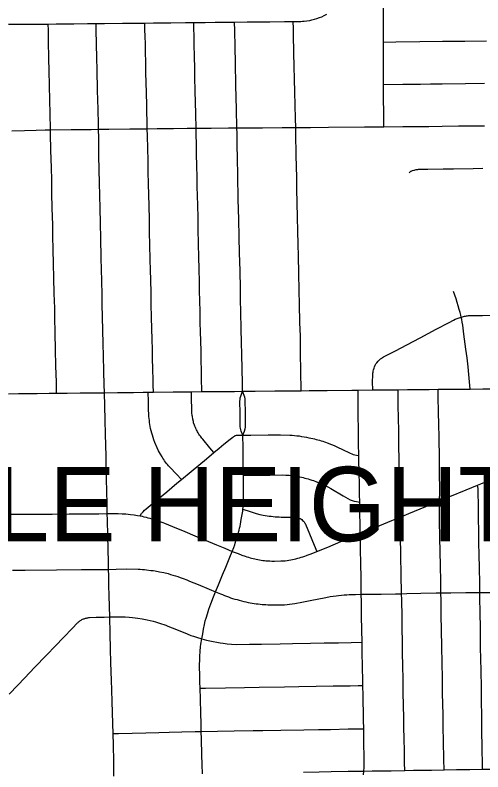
# Model space of a CAD drawing. Extents: x 0 to 34, y 0 to 22.
# Drawn here: x 2.953 to 3.548, y 19.442 to 20.406 of the extents above; entities that cross this region are included whole.
import ezdxf

# ---------------------------------------------------------------- set-up
doc = ezdxf.new("R2010")
doc.units = 0
for name, color, linetype in [('GM_X_City_Street', 7, 'Continuous'), ('GM_X_Corporation_Text', 7, 'Continuous'), ('GM_X_State_Route', 7, 'Continuous')]:
    doc.layers.add(name, color=color, linetype=linetype)

msp = doc.modelspace()

# ---------------------------------------------------------------- linework, layer by layer
at = {"layer": 'GM_X_City_Street'}
for p, q in [((3.17725, 19.92651), (3.19038, 19.9266)), ((3.12227, 19.92591), (3.12865, 19.92602))]:
    msp.add_line(p, q, dxfattribs=at)
for points in [[(3.42223, 20.26388), (3.42199, 20.31784), (3.42193, 20.33158), (3.42179, 20.36208), (3.42175, 20.3717), (3.42163, 20.41614), (3.42168, 20.43603)], [(2.94423, 20.39438), (2.96155, 20.39449), (2.97782, 20.39459), (2.99479, 20.3947), (3.00499, 20.3948), (3.02745, 20.395), (3.04483, 20.39525), (3.05581, 20.39539), (3.06637, 20.39548), (3.08928, 20.39564), (3.10812, 20.39578), (3.11781, 20.39591), (3.12868, 20.39604), (3.15111, 20.39628), (3.16957, 20.39649), (3.18009, 20.3966), (3.19451, 20.39676), (3.2073, 20.3969), (3.22292, 20.39707), (3.23217, 20.39717), (3.24828, 20.39733), (3.27721, 20.39763), (3.29566, 20.39782), (3.30678, 20.39793), (3.31425, 20.39804), (3.31638, 20.39812), (3.3188, 20.39828), (3.32089, 20.39846), (3.32426, 20.39884), (3.32787, 20.3994), (3.33053, 20.39992), (3.33381, 20.40081), (3.33703, 20.40181), (3.34025, 20.4029), (3.34319, 20.40409), (3.34604, 20.40542), (3.34957, 20.40723)], [(3.0054, 19.92458), (3.0051, 19.93869), (3.00464, 19.9597), (3.0042, 19.97977), (3.00363, 20.00142), (3.00323, 20.02112), (3.00299, 20.03301), (3.0025, 20.05176), (3.002, 20.07139), (3.00162, 20.08944), (3.00125, 20.10782), (3.00083, 20.12461), (3.00047, 20.13909), (2.99998, 20.16036), (2.99955, 20.17923), (2.99918, 20.19603), (2.99883, 20.21195), (2.99827, 20.23373), (2.99777, 20.25531), (2.99766, 20.25996), (2.9972, 20.28124), (2.99685, 20.29727), (2.9964, 20.31703), (2.99593, 20.33466), (2.99561, 20.35122), (2.99517, 20.37255), (2.99493, 20.38678), (2.99479, 20.3947)], [(3.07841, 19.43691), (3.0782, 19.45599), (3.07782, 19.47641), (3.07754, 19.49136), (3.07718, 19.50384), (3.07666, 19.51847), (3.07618, 19.53146), (3.07561, 19.54714), (3.07519, 19.55865), (3.07467, 19.58195), (3.07429, 19.59862), (3.07379, 19.61874), (3.07332, 19.63968), (3.07292, 19.65289), (3.0725, 19.66685), (3.07211, 19.67996), (3.07183, 19.69189), (3.07164, 19.70035), (3.07143, 19.70939), (3.07104, 19.72586), (3.07065, 19.74325), (3.07021, 19.76311), (3.07003, 19.77135), (3.06978, 19.78346), (3.06942, 19.80013), (3.06911, 19.8149), (3.06871, 19.83074), (3.06837, 19.84445), (3.06804, 19.85847), (3.06771, 19.87249), (3.06727, 19.89028), (3.06681, 19.90855), (3.0664, 19.92526), (3.06602, 19.9358), (3.06562, 19.95207), (3.06512, 19.97248), (3.06477, 19.98689), (3.06432, 20.00513), (3.06402, 20.02099), (3.06368, 20.03855), (3.06348, 20.04907), (3.06295, 20.06878), (3.06266, 20.08151), (3.06229, 20.09734), (3.06185, 20.12174), (3.06136, 20.14117), (3.06097, 20.16036), (3.06065, 20.17624), (3.06028, 20.19237), (3.05982, 20.20888), (3.05939, 20.22726), (3.05909, 20.24926), (3.0589, 20.26067), (3.05872, 20.26658), (3.05818, 20.28626), (3.05753, 20.31019), (3.05697, 20.33701), (3.05667, 20.35136), (3.05632, 20.36946), (3.05598, 20.38673), (3.05581, 20.39539)], [(3.12865, 19.92602), (3.1284, 19.93498), (3.12822, 19.94184), (3.12797, 19.95527), (3.12769, 19.96921), (3.12739, 19.98042), (3.12717, 19.9931), (3.12684, 20.00693), (3.12638, 20.02106), (3.12601, 20.03798), (3.1257, 20.05193), (3.12531, 20.06961), (3.12503, 20.08102), (3.12475, 20.09529), (3.12436, 20.11298), (3.12395, 20.12999), (3.12356, 20.14624), (3.12319, 20.16287), (3.12283, 20.17772), (3.12252, 20.19067), (3.1222, 20.20678), (3.12185, 20.22076), (3.12143, 20.23604), (3.12109, 20.25245), (3.1209, 20.26146), (3.12065, 20.27118), (3.12041, 20.28249), (3.12019, 20.29186), (3.11986, 20.30688), (3.11954, 20.32061), (3.11929, 20.33206), (3.11899, 20.34579), (3.11877, 20.35936), (3.11852, 20.369), (3.11816, 20.37936), (3.11799, 20.38737), (3.11781, 20.39591)], [(3.19038, 19.9266), (3.19005, 19.94365), (3.18984, 19.9546), (3.18961, 19.96539), (3.18936, 19.97754), (3.18902, 19.99182), (3.18877, 20.00228), (3.18849, 20.01507), (3.18817, 20.02933), (3.18791, 20.04134), (3.18761, 20.05569), (3.1874, 20.06575), (3.18693, 20.08328), (3.18659, 20.0973), (3.18617, 20.11526), (3.18584, 20.13288), (3.18559, 20.1467), (3.18518, 20.16543), (3.18497, 20.1747), (3.18464, 20.18903), (3.18441, 20.19894), (3.1841, 20.21487), (3.18383, 20.22835), (3.18356, 20.24159), (3.1833, 20.25425), (3.18316, 20.26207), (3.18273, 20.27984), (3.18228, 20.29547), (3.182, 20.3087), (3.18159, 20.32734), (3.18136, 20.33809), (3.18103, 20.3538), (3.18072, 20.36828), (3.18045, 20.37989), (3.18026, 20.38884), (3.18009, 20.3966)], [(3.24242, 19.92706), (3.2422, 19.93711), (3.2418, 19.95615), (3.24142, 19.97369), (3.24108, 19.98955), (3.24069, 20.00626), (3.24017, 20.02807), (3.23985, 20.04336), (3.23954, 20.05802), (3.23907, 20.08034), (3.23857, 20.10359), (3.23814, 20.12322), (3.23755, 20.14612), (3.23689, 20.17122), (3.23628, 20.20201), (3.23585, 20.22374), (3.23552, 20.24057), (3.23523, 20.25546), (3.23509, 20.26254), (3.23452, 20.28626), (3.23379, 20.31664), (3.23318, 20.34524), (3.23276, 20.36523), (3.23231, 20.38636), (3.23217, 20.39717)], [(3.31686, 19.92787), (3.3167, 19.95331), (3.31626, 19.97514), (3.31588, 19.99717), (3.31544, 20.01467), (3.31484, 20.03789), (3.3144, 20.05495), (3.31392, 20.07798), (3.31348, 20.09862), (3.31312, 20.11498), (3.31278, 20.13046), (3.31238, 20.14906), (3.31189, 20.16646), (3.31151, 20.18501), (3.31122, 20.19946), (3.31066, 20.22731), (3.31009, 20.25549), (3.30993, 20.263), (3.30966, 20.2744), (3.30927, 20.2914), (3.3089, 20.30858), (3.30856, 20.32425), (3.3082, 20.34115), (3.30778, 20.35762), (3.30715, 20.38184), (3.30698, 20.38883), (3.30678, 20.39793)], [(3.42175, 20.3717), (3.43748, 20.37192), (3.46791, 20.37234), (3.49679, 20.37274), (3.52518, 20.37303), (3.55308, 20.37332)], [(3.42199, 20.31784), (3.44652, 20.31809), (3.46902, 20.31832), (3.48179, 20.31841), (3.49646, 20.31857), (3.52603, 20.3189), (3.55051, 20.31923)], [(2.94842, 20.25889), (2.96474, 20.25935), (2.97947, 20.2597), (2.99091, 20.2599), (2.99766, 20.25996), (3.02414, 20.26031), (3.0493, 20.26057), (3.0589, 20.26067), (3.07213, 20.26081), (3.09852, 20.26114), (3.1209, 20.26146), (3.13347, 20.26159), (3.15412, 20.26181), (3.17161, 20.26197), (3.18316, 20.26207), (3.20224, 20.26224), (3.2243, 20.26244), (3.23509, 20.26254), (3.26766, 20.26271), (3.29276, 20.26288), (3.30993, 20.263), (3.32879, 20.26309), (3.35191, 20.26335), (3.39769, 20.26363), (3.42223, 20.26388), (3.44656, 20.26406), (3.46164, 20.2642), (3.4797, 20.26436), (3.49658, 20.2646), (3.51731, 20.26489), (3.52594, 20.26501), (3.53385, 20.26511), (3.55053, 20.26523)], [(3.45431, 20.20514), (3.45483, 20.20574), (3.45524, 20.20614), (3.45568, 20.20652), (3.45616, 20.20686), (3.45665, 20.20717), (3.45717, 20.20743), (3.4577, 20.20766), (3.45886, 20.20805), (3.46038, 20.20854), (3.46126, 20.20882), (3.46229, 20.20908), (3.46332, 20.20929), (3.46436, 20.20947), (3.46541, 20.20962), (3.46645, 20.20972), (3.46751, 20.20979), (3.47836, 20.20997), (3.49779, 20.21031), (3.51105, 20.21047), (3.53605, 20.21085), (3.54836, 20.21105)], [(3.53231, 19.92991), (3.53134, 19.93923), (3.53044, 19.94844), (3.52956, 19.95818), (3.52827, 19.96978), (3.52686, 19.98059), (3.5242, 19.99969), (3.52267, 20.01112), (3.52207, 20.01509), (3.52147, 20.01852), (3.52082, 20.02162), (3.52024, 20.02415), (3.51942, 20.02741), (3.5183, 20.03132), (3.51704, 20.0357), (3.51573, 20.04023), (3.51425, 20.04472), (3.51261, 20.04948), (3.51091, 20.05421)], [(3.40816, 19.92873), (3.40798, 19.93894), (3.40816, 19.94764), (3.40838, 19.94997), (3.40855, 19.95125), (3.40875, 19.95256), (3.40913, 19.95435), (3.40983, 19.95656), (3.41049, 19.95823), (3.41136, 19.96026), (3.41223, 19.96185), (3.41339, 19.96346), (3.41496, 19.96529), (3.41662, 19.96703), (3.41807, 19.9682), (3.4195, 19.9693), (3.42064, 19.97003), (3.42194, 19.97076), (3.42943, 19.97457), (3.43689, 19.97852), (3.45146, 19.98624), (3.4687, 19.99521), (3.48891, 20.00602), (3.50543, 20.01486), (3.51074, 20.01759), (3.51321, 20.01875), (3.51544, 20.0197), (3.5168, 20.02025), (3.51818, 20.02076), (3.51957, 20.02123), (3.52082, 20.02162), (3.52239, 20.02206), (3.52382, 20.02241), (3.5251, 20.02268), (3.52638, 20.02293), (3.52766, 20.02313), (3.52896, 20.02329), (3.53026, 20.02341), (3.53155, 20.0235), (3.5477, 20.02368), (3.566, 20.02388)], [(3.20585, 19.84894), (3.20053, 19.85521), (3.19148, 19.86622), (3.19045, 19.86747), (3.18946, 19.86873), (3.18851, 19.87), (3.18759, 19.87131), (3.18671, 19.87263), (3.18585, 19.87398), (3.18504, 19.87535), (3.18426, 19.87674), (3.18352, 19.87815), (3.18281, 19.87958), (3.18214, 19.88102), (3.1815, 19.88248), (3.18093, 19.88391), (3.18001, 19.88693), (3.1796, 19.88849), (3.17889, 19.89163), (3.17832, 19.89479), (3.1781, 19.89638), (3.17775, 19.89958), (3.17756, 19.9028), (3.17732, 19.91909), (3.17725, 19.92651)], [(3.24275, 19.87128), (3.24057, 19.87645), (3.24002, 19.87792), (3.23947, 19.87998), (3.23926, 19.88179), (3.23907, 19.89926), (3.2389, 19.91467), (3.23906, 19.91676), (3.23941, 19.91867), (3.24015, 19.92104), (3.24242, 19.92706)], [(3.24275, 19.87128), (3.24472, 19.87625), (3.24574, 19.8794), (3.24603, 19.88133), (3.24613, 19.88334), (3.24592, 19.90027), (3.24574, 19.91554), (3.24548, 19.91738), (3.24498, 19.91952), (3.24434, 19.92159), (3.24242, 19.92706)], [(3.39636, 19.43857), (3.39687, 19.44349), (3.39725, 19.44835), (3.39711, 19.46462), (3.39692, 19.47572), (3.39678, 19.4876), (3.39656, 19.49722), (3.3964, 19.50875), (3.39624, 19.51987), (3.39601, 19.53019), (3.3958, 19.53969), (3.39551, 19.55249), (3.39537, 19.55896), (3.395, 19.57584), (3.39471, 19.59523), (3.39453, 19.60744), (3.39426, 19.62334), (3.39398, 19.64059), (3.39363, 19.65919), (3.39344, 19.66862), (3.39328, 19.68847), (3.39293, 19.70894), (3.39265, 19.72448), (3.3924, 19.73884), (3.39228, 19.74595), (3.39209, 19.75597), (3.39175, 19.77347), (3.3915, 19.7861), (3.39132, 19.79623), (3.39112, 19.80803), (3.39083, 19.82412), (3.39039, 19.83978), (3.39035, 19.84553), (3.39013, 19.86078), (3.38999, 19.86989), (3.38987, 19.88198), (3.38969, 19.89276), (3.38938, 19.91129), (3.38935, 19.92864)], [(3.44882, 19.44425), (3.44862, 19.45407), (3.44834, 19.4691), (3.44805, 19.48461), (3.44777, 19.4996), (3.44757, 19.5105), (3.44728, 19.52771), (3.44703, 19.54257), (3.44672, 19.56061), (3.44644, 19.57729), (3.44616, 19.5942), (3.4459, 19.60924), (3.44565, 19.62414), (3.44538, 19.64003), (3.44502, 19.66148), (3.44489, 19.66934), (3.44439, 19.6943), (3.44398, 19.71724), (3.44351, 19.74372), (3.44331, 19.75991), (3.44323, 19.76692), (3.443, 19.77715), (3.4426, 19.79789), (3.44228, 19.81435), (3.4421, 19.82334), (3.44193, 19.8342), (3.44172, 19.84361), (3.44147, 19.85426), (3.44132, 19.86636), (3.44115, 19.87777), (3.4409, 19.89216), (3.44066, 19.90991), (3.44047, 19.92138), (3.44035, 19.92907)], [(3.49916, 19.44511), (3.49873, 19.45866), (3.49827, 19.48142), (3.49792, 19.49953), (3.49763, 19.515), (3.49737, 19.52917), (3.49712, 19.54209), (3.49678, 19.56275), (3.49648, 19.58027), (3.4961, 19.60257), (3.49576, 19.62267), (3.49533, 19.64243), (3.49505, 19.66066), (3.49491, 19.67036), (3.49466, 19.68388), (3.49425, 19.70595), (3.4939, 19.72178), (3.49347, 19.74181), (3.49325, 19.76126), (3.49332, 19.78764), (3.49358, 19.79911), (3.49323, 19.82595), (3.49299, 19.84313), (3.49257, 19.86644), (3.49221, 19.88688), (3.49194, 19.89856), (3.49151, 19.92214), (3.49148, 19.92963)], [(3.1647, 19.81497), (3.15815, 19.82162), (3.14974, 19.83032), (3.14811, 19.83222), (3.14681, 19.83373), (3.14541, 19.83533), (3.1442, 19.83692), (3.14303, 19.83854), (3.14189, 19.84018), (3.14077, 19.84183), (3.13969, 19.84352), (3.13766, 19.8469), (3.13543, 19.85107), (3.13349, 19.85496), (3.13057, 19.86169), (3.12931, 19.86516), (3.12839, 19.86807), (3.1275, 19.871), (3.12666, 19.87393), (3.12585, 19.87689), (3.12514, 19.8798), (3.12467, 19.88225), (3.12427, 19.88483), (3.12391, 19.88741), (3.12359, 19.89), (3.12331, 19.89258), (3.12308, 19.89516), (3.12285, 19.89889), (3.12266, 19.90264), (3.12251, 19.90639), (3.12239, 19.91015), (3.12232, 19.91424), (3.12227, 19.92591)], [(3.11172, 19.76838), (3.11377, 19.77133), (3.11574, 19.77367), (3.11747, 19.7755), (3.11937, 19.77732), (3.12218, 19.77965), (3.13193, 19.78776), (3.1457, 19.79914), (3.15871, 19.80998), (3.1647, 19.81497), (3.17665, 19.82487), (3.18654, 19.83307), (3.19636, 19.84121), (3.20585, 19.84894), (3.2127, 19.85468), (3.21861, 19.85962), (3.22637, 19.86606), (3.22836, 19.8676), (3.2298, 19.86867), (3.23054, 19.86919), (3.23121, 19.86965), (3.23183, 19.87002), (3.23245, 19.87034), (3.23308, 19.8706), (3.23384, 19.87082), (3.23458, 19.87101), (3.23536, 19.87112), (3.23633, 19.87119), (3.24275, 19.87128)], [(3.19109, 19.44013), (3.19078, 19.45207), (3.19045, 19.46425), (3.18989, 19.48426), (3.18969, 19.49396), (3.18942, 19.50451), (3.18911, 19.5167), (3.18861, 19.53544), (3.18825, 19.54895), (3.18807, 19.55691), (3.18772, 19.56945), (3.18764, 19.57224), (3.18753, 19.57843), (3.18766, 19.58549), (3.18782, 19.58944), (3.18823, 19.59629), (3.1888, 19.6018), (3.18922, 19.60515), (3.19028, 19.61183), (3.19153, 19.6183), (3.19262, 19.62424), (3.1938, 19.63033), (3.19482, 19.63471), (3.19573, 19.63814), (3.19754, 19.6439), (3.19951, 19.64983), (3.2019, 19.65655), (3.20517, 19.6652), (3.20782, 19.67184), (3.21149, 19.68074), (3.2167, 19.6934), (3.22077, 19.70328), (3.22598, 19.71582), (3.22907, 19.72326), (3.23103, 19.72799), (3.23234, 19.7317), (3.23302, 19.73379), (3.23435, 19.73806), (3.23514, 19.74048), (3.23591, 19.74292), (3.23662, 19.74538), (3.2373, 19.74785), (3.23793, 19.75033), (3.23852, 19.75282), (3.23907, 19.75532), (3.23958, 19.75783), (3.24066, 19.76392), (3.24138, 19.76817), (3.24247, 19.77454), (3.24279, 19.77695), (3.24328, 19.78087), (3.24345, 19.78413), (3.24338, 19.81412), (3.24329, 19.82002), (3.24317, 19.83073), (3.24309, 19.84469), (3.24292, 19.85502), (3.24275, 19.87128)], [(3.24275, 19.87128), (3.25301, 19.87137), (3.27501, 19.87148), (3.29074, 19.87155), (3.30266, 19.87132), (3.30562, 19.87112), (3.30857, 19.87087), (3.3115, 19.87057), (3.31452, 19.87015), (3.31755, 19.86968), (3.32057, 19.86917), (3.32359, 19.86862), (3.32661, 19.86801), (3.33181, 19.86691), (3.33395, 19.86641), (3.3361, 19.86588), (3.33822, 19.8653), (3.34035, 19.86469), (3.34245, 19.86405), (3.34455, 19.86337), (3.34663, 19.86264), (3.35151, 19.86085), (3.35426, 19.8598), (3.357, 19.85871), (3.35972, 19.85757), (3.36242, 19.8564), (3.36511, 19.85519), (3.36778, 19.85393), (3.37043, 19.85264), (3.37759, 19.84897), (3.38335, 19.84672), (3.38519, 19.84623), (3.38723, 19.84583), (3.39035, 19.84553)], [(3.24329, 19.82002), (3.25644, 19.82016), (3.27697, 19.82037), (3.29268, 19.82052), (3.29721, 19.82042), (3.29947, 19.82031), (3.30173, 19.82015), (3.30399, 19.81994), (3.30624, 19.81969), (3.30849, 19.81939), (3.31074, 19.81905), (3.31296, 19.81864), (3.31516, 19.81819), (3.31735, 19.81771), (3.31953, 19.8172), (3.32171, 19.81664), (3.32387, 19.81605), (3.32604, 19.81543), (3.32818, 19.81477), (3.33032, 19.81408), (3.33244, 19.81334), (3.33641, 19.81192), (3.34097, 19.81001), (3.34583, 19.80765), (3.35073, 19.80524), (3.35466, 19.8031), (3.3703, 19.79414), (3.37949, 19.78906), (3.38203, 19.78797), (3.38461, 19.78719), (3.38733, 19.78663), (3.3915, 19.7861)], [(2.94512, 19.77043), (2.97389, 19.77054), (2.99985, 19.77076), (3.0214, 19.77094), (3.04314, 19.77112), (3.05911, 19.77125), (3.07003, 19.77135), (3.08403, 19.77127), (3.089, 19.77113), (3.09379, 19.77087), (3.09674, 19.77061), (3.09956, 19.77035), (3.10434, 19.76971), (3.10849, 19.76904), (3.11172, 19.76838), (3.11432, 19.76787), (3.11659, 19.76738), (3.11939, 19.76672), (3.12168, 19.76616), (3.12409, 19.76553), (3.12648, 19.76488), (3.12866, 19.76425), (3.13108, 19.76349), (3.13349, 19.76268), (3.13588, 19.76185), (3.13826, 19.76098), (3.14063, 19.76007), (3.14297, 19.75913), (3.15304, 19.75502), (3.16871, 19.74852), (3.18156, 19.74317), (3.20918, 19.73168), (3.21964, 19.72732), (3.22907, 19.72326), (3.23654, 19.72041), (3.2415, 19.71852), (3.24563, 19.71706), (3.24789, 19.71629), (3.24994, 19.71567), (3.25181, 19.71516), (3.25372, 19.71468), (3.25573, 19.71415), (3.25776, 19.71366), (3.25979, 19.71322), (3.26389, 19.71244), (3.26594, 19.71211), (3.26801, 19.71182), (3.27007, 19.71156), (3.27213, 19.71135), (3.27455, 19.71117), (3.277, 19.71104), (3.27961, 19.71088), (3.28305, 19.71081), (3.29116, 19.71102), (3.2943, 19.71121), (3.29642, 19.71139), (3.29898, 19.71168), (3.30138, 19.71208), (3.3036, 19.71247), (3.30585, 19.71291), (3.3081, 19.71339), (3.31035, 19.71391), (3.31258, 19.71446), (3.3148, 19.71505), (3.31702, 19.71568), (3.31922, 19.71634), (3.32141, 19.71704), (3.32356, 19.71778), (3.32475, 19.71823), (3.32981, 19.72014), (3.3368, 19.72291), (3.35082, 19.72873), (3.3674, 19.73561), (3.38152, 19.74147), (3.39228, 19.74595), (3.40507, 19.75129), (3.41723, 19.75638), (3.43262, 19.76266), (3.44323, 19.76692), (3.4539, 19.77132), (3.46869, 19.77742), (3.48298, 19.78335), (3.49332, 19.78764), (3.50618, 19.79293), (3.52692, 19.80147), (3.54155, 19.80749), (3.54576, 19.80918), (3.56007, 19.81528)], [(3.5481, 19.44588), (3.54796, 19.45317), (3.54762, 19.47091), (3.54719, 19.49758), (3.5469, 19.51372), (3.54673, 19.53249), (3.54657, 19.5509), (3.54609, 19.57009), (3.54567, 19.58717), (3.54552, 19.60017), (3.54515, 19.62488), (3.54484, 19.64584), (3.54465, 19.66352), (3.54457, 19.67097), (3.5444, 19.68176), (3.54401, 19.70312), (3.54354, 19.71814), (3.54343, 19.73501), (3.5432, 19.74988), (3.54285, 19.76443), (3.54263, 19.77916), (3.54245, 19.80107), (3.5422, 19.80347), (3.54155, 19.80749)], [(3.24279, 19.77695), (3.25194, 19.77393), (3.25981, 19.77158), (3.26443, 19.77037), (3.26842, 19.76948), (3.27099, 19.76902), (3.27352, 19.76861), (3.27605, 19.76824), (3.27859, 19.76792), (3.28114, 19.76764), (3.28369, 19.7674), (3.28624, 19.7672), (3.2888, 19.76705), (3.29139, 19.76694), (3.31089, 19.76682), (3.31202, 19.76651), (3.31294, 19.7662), (3.31435, 19.76564), (3.31504, 19.7653), (3.31571, 19.76493), (3.31635, 19.76454), (3.31759, 19.76365), (3.3188, 19.76265), (3.31978, 19.76171), (3.32068, 19.76067), (3.32109, 19.76011), (3.32147, 19.75955), (3.32214, 19.75835), (3.32243, 19.75773), (3.32763, 19.74537), (3.33347, 19.73106), (3.3368, 19.72291)], [(2.94943, 19.69929), (2.96553, 19.69942), (3.00532, 19.69975), (3.0373, 19.70004), (3.06376, 19.70029), (3.07164, 19.70035), (3.08111, 19.70055), (3.09417, 19.70083), (3.10923, 19.70069), (3.11196, 19.70052), (3.1147, 19.70031), (3.11742, 19.70006), (3.12014, 19.69976), (3.12564, 19.69907), (3.12838, 19.69868), (3.13112, 19.69825), (3.13657, 19.69728), (3.142, 19.69615), (3.14737, 19.69489), (3.15049, 19.694), (3.15362, 19.69307), (3.15674, 19.6921), (3.15986, 19.69109), (3.16295, 19.69004), (3.16684, 19.68862), (3.17122, 19.68687), (3.17491, 19.68538), (3.18557, 19.68099), (3.19994, 19.67506), (3.20782, 19.67184), (3.21412, 19.66924), (3.21665, 19.6682), (3.21922, 19.66716), (3.2218, 19.66617), (3.2244, 19.66521), (3.22701, 19.66429), (3.22963, 19.66343), (3.23242, 19.66258), (3.23523, 19.66177), (3.23806, 19.66099), (3.2409, 19.66026), (3.24375, 19.65956), (3.24661, 19.6589), (3.24946, 19.65829), (3.25195, 19.65781), (3.25445, 19.65737), (3.25696, 19.65698), (3.25947, 19.65662), (3.262, 19.65629), (3.26452, 19.65601), (3.26706, 19.65577), (3.26958, 19.65557), (3.27212, 19.65541), (3.27466, 19.65529), (3.27991, 19.65514), (3.29576, 19.65536), (3.29903, 19.65555), (3.30218, 19.65591), (3.30526, 19.65629), (3.30892, 19.65677), (3.31779, 19.65841), (3.32838, 19.6605), (3.34814, 19.66451), (3.35402, 19.66558), (3.35778, 19.66622), (3.3615, 19.66673), (3.36458, 19.66709), (3.36831, 19.6675), (3.37191, 19.66781), (3.37502, 19.66801), (3.37818, 19.66819), (3.38203, 19.6683), (3.38608, 19.66842), (3.39344, 19.66862), (3.4036, 19.66875), (3.41873, 19.66896), (3.4371, 19.66922), (3.44489, 19.66934), (3.45171, 19.66948), (3.46916, 19.66985), (3.48894, 19.67024), (3.49491, 19.67036), (3.50766, 19.67046), (3.52651, 19.6708), (3.53789, 19.671), (3.54457, 19.67097), (3.56853, 19.67094)], [(2.94506, 19.54135), (2.95598, 19.55283), (2.96437, 19.56163), (2.97787, 19.57572), (2.99229, 19.59076), (3.00453, 19.60354), (3.01388, 19.61325), (3.0261, 19.62605), (3.03134, 19.63149), (3.03203, 19.63219), (3.03276, 19.63287), (3.03353, 19.63353), (3.03431, 19.63415), (3.03513, 19.63473), (3.03597, 19.63529), (3.03683, 19.63581), (3.03771, 19.63629), (3.03861, 19.63673), (3.03953, 19.63714), (3.04047, 19.6375), (3.04142, 19.63783), (3.04238, 19.63812), (3.04336, 19.63836), (3.04434, 19.63857), (3.04533, 19.63873), (3.04633, 19.63886), (3.04732, 19.63894), (3.056, 19.63931), (3.06617, 19.63953), (3.07332, 19.63968), (3.08727, 19.63981), (3.09274, 19.63968), (3.09796, 19.63943), (3.10211, 19.63909), (3.10893, 19.63835), (3.11433, 19.6375), (3.12086, 19.63619), (3.12846, 19.63433), (3.13119, 19.63357), (3.13389, 19.63277), (3.13657, 19.63193), (3.13924, 19.63103), (3.14189, 19.6301), (3.14453, 19.62912), (3.14716, 19.62809), (3.15801, 19.6237), (3.17178, 19.61805), (3.1765, 19.6163), (3.17962, 19.61517), (3.18351, 19.61387), (3.19028, 19.61183), (3.19616, 19.61029), (3.20478, 19.60842), (3.2095, 19.60752), (3.2136, 19.60684), (3.21752, 19.60629), (3.22259, 19.60569), (3.22805, 19.60522), (3.23508, 19.60479), (3.25119, 19.60492), (3.26637, 19.60514), (3.29001, 19.60556), (3.30592, 19.60589), (3.32873, 19.60629), (3.34631, 19.6066), (3.36447, 19.60691), (3.38076, 19.6072), (3.39453, 19.60744)], [(3.18825, 19.54895), (3.19515, 19.54908), (3.22074, 19.54955), (3.24489, 19.55), (3.26325, 19.55029), (3.29568, 19.55083), (3.31386, 19.55113), (3.33615, 19.5515), (3.3577, 19.55186), (3.37942, 19.55222), (3.38966, 19.55239), (3.39551, 19.55249)], [(3.07754, 19.49136), (3.08421, 19.49151), (3.10185, 19.49191), (3.11923, 19.49231), (3.13561, 19.49269), (3.14887, 19.493), (3.16495, 19.49337), (3.18198, 19.49377), (3.18969, 19.49396), (3.21032, 19.49432), (3.23175, 19.49469), (3.2556, 19.4951), (3.26818, 19.49528), (3.29102, 19.49559), (3.32052, 19.49608), (3.33914, 19.49638), (3.35448, 19.49663), (3.37686, 19.49707), (3.38969, 19.49717), (3.39656, 19.49722)], [(3.32001, 19.44218), (3.33994, 19.44251), (3.35528, 19.44282), (3.3768, 19.44326), (3.39076, 19.44342), (3.39687, 19.44349), (3.40717, 19.44364), (3.43149, 19.444), (3.44882, 19.44425), (3.45986, 19.44444), (3.48292, 19.44483), (3.49916, 19.44511), (3.51478, 19.44536), (3.53161, 19.44562), (3.5481, 19.44588), (3.56154, 19.44605), (3.57346, 19.44621)]]:
    msp.add_lwpolyline(points, dxfattribs=at)
at = {"layer": 'GM_X_State_Route'}
for p, q in [((3.17725, 19.92651), (3.19038, 19.9266)), ((3.12227, 19.92591), (3.12865, 19.92602))]:
    msp.add_line(p, q, dxfattribs=at)
for points in [[(3.12865, 19.92602), (3.15377, 19.92628), (3.17725, 19.92651)], [(3.19038, 19.9266), (3.20507, 19.92673), (3.23201, 19.92696), (3.24242, 19.92706), (3.25821, 19.92722), (3.28321, 19.92748), (3.30168, 19.92766), (3.31686, 19.92787), (3.32694, 19.92798), (3.34994, 19.92821), (3.38149, 19.92851), (3.38935, 19.92864), (3.40816, 19.92873), (3.42005, 19.92885), (3.43043, 19.92896), (3.44035, 19.92907), (3.45249, 19.9292), (3.46617, 19.92935), (3.48007, 19.9295), (3.49148, 19.92963), (3.50563, 19.92972), (3.52136, 19.92983), (3.53231, 19.92991), (3.54816, 19.93008), (3.56778, 19.93029)], [(2.9442, 19.92395), (2.95692, 19.92409), (2.9807, 19.92433), (2.99599, 19.92448), (3.0054, 19.92458), (3.01908, 19.92473), (3.03536, 19.92491), (3.05713, 19.92515), (3.0664, 19.92526), (3.08294, 19.92546), (3.10321, 19.9257), (3.1156, 19.92584), (3.12227, 19.92591)]]:
    msp.add_lwpolyline(points, dxfattribs=at)

# ---------------------------------------------------------------- texts
at = {"layer": 'GM_X_Corporation_Text'}
msp.add_text('MAPLE HEIGHTS', height=0.094697, rotation=0.00001, dxfattribs=at).set_placement((2.65114, 19.73619))

doc.saveas('drawing.dxf')
